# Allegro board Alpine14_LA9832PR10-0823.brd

Outline 316.05 x 177.2 mm; copper layers: TOP, GND1, IN1, VCC, IN2, IN3, GND2, BOTTOM. Coordinates in mm from the lower left corner of the outline.
Outline path: 0,104.74 arc(0.44,105.8) 1.5,106.24 28.86,106.24 arc(29.54,106.08) 30.08,105.62 arc(32.3,104.49) 34.52,105.62 arc(35.06,106.08) 35.74,106.24 50.28,106.24 arc(72.2,115.32) 81.28,137.24 81.28,142.24 arc(81.02,146.24) 80.25,150.17 arc(80.21,150.36) 80.2,150.55 80.2,158.02 arc(80.1,158.56) 79.81,159.03 74.64,164.67 arc(74.35,165.14) 74.25,165.68 74.25,173.8 arc(74.69,174.86) 75.75,175.3 111.8,175.3 arc(112.43,175.16) 112.95,174.76 113.55,174.04 arc(114.07,173.64) 114.7,173.5 130.83,173.5 arc(131.19,173.54) 131.53,173.67 133.07,174.48 arc(133.41,174.61) 133.77,174.65 198.63,174.65 arc(198.99,174.61) 199.33,174.48 200.87,173.67 arc(201.21,173.54) 201.57,173.5 219.2,173.5 arc(219.83,173.64) 220.35,174.04 220.95,174.76 arc(221.47,175.16) 222.1,175.3 282.93,175.3 arc(283.5,175.41) 283.99,175.74 285.01,176.76 arc(285.5,177.09) 286.07,177.2 314.55,177.2 arc(315.61,176.76) 316.05,175.7 316.05,146.8 arc(315.76,146.09) 315.05,145.8 313.55,145.8 arc(312.84,145.51) 312.55,144.8 312.55,144.6 arc(312.26,143.89) 311.55,143.6 237.58,143.6 arc(237.01,143.49) 236.52,143.16 211.9,118.54 arc(211.41,118.21) 210.84,118.1 198.85,118.1 arc(197.79,117.66) 197.35,116.6 197.35,77.49 arc(197.05,76.59) 196.26,76.05 arc(193.35,72.2) 196.26,68.35 arc(197.05,67.81) 197.35,66.91 197.35,62.95 arc(197.64,62.24) 198.35,61.95 198.85,61.95 arc(199.56,61.66) 199.85,60.95 199.85,15 arc(199.41,13.94) 198.35,13.5 193.9,13.5 arc(192.84,13.06) 192.4,12 192.4,2.5 arc(191.96,1.44) 190.9,1 100.9,1 arc(99.84,1.44) 99.4,2.5 99.4,8.4 arc(98.96,9.46) 97.9,9.9 16.8,9.9 arc(15.74,9.46) 15.3,8.4 15.3,1.5 arc(14.86,0.44) 13.8,0 6.9,0 arc(4.07,1.17) 2.9,4 2.9,8.75 arc(2.75,9.11) 2.4,9.25 2.2,9.25 arc(1.85,9.4) 1.7,9.75 1.7,37 arc(1.63,37.26) 1.44,37.44 arc(0.5,39.02) 1.44,40.6 arc(1.63,40.78) 1.7,41.04 1.7,65.25 arc(1.85,65.61) 2.2,65.75 2.4,65.75 arc(2.75,65.9) 2.9,66.25 2.9,68.6 arc(3.05,68.96) 3.4,69.1 13.96,69.1 arc(14.46,69.6) 13.96,70.1 13.46,70.1 arc(13.1,70.25) 12.96,70.6 12.96,81.1 arc(13.1,81.46) 13.46,81.6 13.96,81.6 arc(14.46,82.1) 13.96,82.6 3.15,82.6 arc(2.8,82.75) 2.65,83.1 2.65,86.55 arc(2.8,86.9) 3.15,87.05 9.93,87.05 arc(10.43,87.55) 9.93,88.05 9.93,101.55 arc(10.43,102.05) 9.93,102.55 0.5,102.55 arc(0.15,102.7) 0,103.05 0,104.74

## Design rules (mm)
net group BC_DAT-EC1117: nets BC_CLK_ECE1117 BC_DAT_ECE1117
net group BC_DAT_ECE5048: nets BC_CLK_ECE5048 BC_DAT_ECE5048
net group CL_LINK: nets PCH_CL_RST1# PCH_CL_RST1#_R
net group CLK_PCIE_EXP: nets CLK_PCIE_EXP CLK_PCIE_EXP#
net group CLK_PCIE_FMC: nets CLK_PCIE_FMC CLK_PCIE_FMC#
net group CLK_PCIE_MINI2: nets CLK_PCIE_MINI2 CLK_PCIE_MINI2#
net group CLK_PCIE_MMI: nets CLK_PCIE_MMI CLK_PCIE_MMI#
net group CLK_PEG_VGA: nets CLK_PEG_VGA CLK_PEG_VGA#
net group CLKA0: nets CLKA0 CLKA0#
net group CLKA1: nets CLKA1 CLKA1#
net group CPU_DPB_CTRLDAT: nets CPU_DPB_CTRLCLK CPU_DPB_CTRLDAT
net group CSS_1: nets CSSN_1 CSSP_1
net group DAT_DDC2_DOCK: nets CLK_DDC2_DOCK DAT_DDC2_DOCK
net group DAT_TP_SIO: nets CLK_TP_SIO DAT_TP_SIO
net group DCIN_JACK: nets +DCIN_JACK -DCIN_JACK
net group DDR_A_DQS0: nets DDR_A_DQS0 DDR_A_DQS#0
net group DDR_A_DQS1: nets DDR_A_DQS1 DDR_A_DQS#1
net group DDR_A_DQS2: nets DDR_A_DQS2 DDR_A_DQS#2
net group DDR_A_DQS3: nets DDR_A_DQS3 DDR_A_DQS#3
net group DDR_A_DQS4: nets DDR_A_DQS4 DDR_A_DQS#4
net group DDR_A_DQS6: nets DDR_A_DQS6 DDR_A_DQS#6
net group DDR_A_DQS7: nets DDR_A_DQS7 DDR_A_DQS#7
net group DDR_B_DQS0: nets DDR_B_DQS0 DDR_B_DQS#0
net group DDR_B_DQS1: nets DDR_B_DQS1 DDR_B_DQS#1
net group DDR_B_DQS2: nets DDR_B_DQS2 DDR_B_DQS#2
net group DDR_B_DQS4: nets DDR_B_DQS4 DDR_B_DQS#4
net group DDR_B_DQS5: nets DDR_B_DQS5 DDR_B_DQS#5
net group DDR_B_DQS6: nets DDR_B_DQS6 DDR_B_DQS#6
net group DDR_B_DQS7: nets DDR_B_DQS7 DDR_B_DQS#7
net group DDR_B_DQS#3: nets DDR_B_DQS3 DDR_B_DQS#3
net group DDR_XDP_SMBCLK_R1: nets DDR_XDP_SMBCLK_R1 DDR_XDP_SMBDAT_R1
net group DIFFPAIR0: nets DDR_A_DQS5 DDR_A_DQS#5
net group DIFFPAIR1: nets SATA_PRX_DTX_N1 SATA_PRX_DTX_P1
net group DIFFPAIR2: nets SATA_PTX_DRX_N1 SATA_PTX_DRX_P1
net group DIFFPAIR3: nets SATA_PRX_DTX_N1_C SATA_PRX_DTX_P1_C
net group DIFFPAIR4: nets SATA_PTX_DRX_N1_C SATA_PTX_DRX_P1_C
net group DIFFPAIR5: nets SATA_PRX_DKTX_N0_C SATA_PRX_DKTX_P0_C
net group DMIC_CLK0: nets DMIC0 DMIC_CLK0
net group DOCK_DCIN_IS: nets DOCK_DCIN_IS+ DOCK_DCIN_IS-
net group DPB_CA_DET: nets DPB_CA_DET DPB_CA_DET#
net group DPC_CA_DET: nets DPC_CA_DET DPC_CA_DET#
net group EDID_DATA_LCD: nets EDID_CLK_LCD EDID_DATA_LCD
net group EDP_CPU_AUX: nets EDP_CPU_AUX EDP_CPU_AUX#
net group EDP_CPU_AUX_C: nets EDP_CPU_AUX#_C EDP_CPU_AUX_C
net group EDP_CPU_LANE_0: nets EDP_CPU_LANE_N0 EDP_CPU_LANE_P0
net group EDP_CPU_LANE_0_C: nets EDP_CPU_LANE_N0_C EDP_CPU_LANE_P0_C
net group EDP_CPU_LANE_1: nets EDP_CPU_LANE_N1 EDP_CPU_LANE_P1
net group EDP_CPU_LANE_1_C: nets EDP_CPU_LANE_N1_C EDP_CPU_LANE_P1_C
net group GPU_SMBCLK: nets GPU_SMBCLK GPU_SMBDAT
net group HUB_USBP1_R_D: nets HUB_USBP1_R_D+ HUB_USBP1_R_D-
net group HUB_USBP4: nets HUB_USBP4+ HUB_USBP4-
net group HUB_USBP4_D: nets HUB_USBP4+_D HUB_USBP4-_D
net group INT_SPK_L: nets INT_SPK_L+ INT_SPK_L-
net group INT_SPK_R: nets INT_SPK_R+ INT_SPK_R-
net group NVVDD_SENSE: nets NVVDD_GND_SENSE NVVDD_SENSE
net group PCH_CL_CLK1: nets PCH_CL_CLK1 PCH_CL_DATA1
net group PCIE_PTX_EXPRX_C: nets PCIE_PTX_EXPRX_N_C PCIE_PTX_EXPRX_P_C
net group PEG_EXP: nets PEG_EXP PEG_EXP#
net group PS2_DAT_TS: nets PS2_CLK_TS PS2_DAT_TS
net group REM_DIODE1_: nets REM_DIODE1_N REM_DIODE1_P
net group REM_DIODE3: nets REM_DIODE3_N REM_DIODE3_P
net group REM_DIODE4_: nets REM_DIODE4_N REM_DIODE4_P
net group SATA_PTX_MSATARX_3: nets SATA_PTX_MSATARX_N3 SATA_PTX_MSATARX_P3
net group SATA_PTX_MSATARX_3_C: nets SATA_PTX_MSATARX_N3_C SATA_PTX_MSATARX_P3_C
net group SENSE: nets VCCSENSE VSSSENSE
net group SMB_15: nets BC_INT#_ECE1117 BC_INT#_ECE5048
net group SR_B: nets SRN_B SRP_B
net group THERMAL: nets REM_DIODE2_N REM_DIODE2_P
net group USB3R4: nets USB3RN4 USB3RP4
net group USB3RP4_D: nets USB3RN4_D- USB3RP4_D+
net group USB3T4: nets USB3TN4 USB3TP4
net group USB3TN1_RP_C: nets USB3TN1_RP_C USB3TP1_RP_C
net group USB3TP1_RP_CL: nets USB3TN1_RP_CL USB3TP1_RP_CL
net group USB3TP4_D: nets USB3TN4_D- USB3TP4_D+
net group USBP0: nets USBP0+ USBP0-
net group USBP2: nets USBP2+ USBP2-
net group 12: nets PCH_OPI_COMP PCH_PCIE_IREF PCH_PCIE_RCOMP SATA_COMP SATA_IREF
net group ASYNC: nets DDR3_DRAMRST# DDR3_DRAMRST#_CPU H_CPU_SVIDALRT# H_PROCHOT# H_PROCHOT#_R H_THERMTRIP# H_THERMTRIP#_R H_VCCST_PWRGD_XDP PECI_EC PECI_EC_R PROCHOT#_EC THERMATRIP2# VCCST_PWRGD VIDALERT_N VIDSCLK VIDSOUT XDP_OBS0_R XDP_OBS1_R
net group CLK-SRC: nets CLK_PCIE_LAN CLK_PCIE_LAN# PCIE_LAN PCIE_LAN# PCIE_MINI2 PCIE_MINI2# PCIE_MMI PCIE_MMI# PEG_VGA PEG_VGA# PEG_VGA_EXP PEG_VGA_EXP#
net group CLK_SINGAL: nets CLK_PCI_DOCK CLK_PCI_FBIN CLK_PCI_LPDEBUG CLK_PCI_MEC CLK_PCI_TPM_TCM EC_32KHZ_ECE5048 EC_32KHZ_ECE5048_R PCI_5048 PCI_CLK_LPC PCI_CLK_LPC_0 PCI_CLK_LPC_1 PCI_FBIN PCI_MEC PCI_TPM_TCM VMM_SPI_CLK
net group CR_LOW: nets DSWODVREN INTRUDER# PCH_DPWROK PCH_INTVRMEN PCH_PCIE_WAKE# PCH_RSMRST#_Q PCH_RSMRST#_R PCH_RTCRST# PM_APWROK SIO_PWRBTN# SIO_RCIN# SRTCRST# SYS_PWROK SYS_PWROK_R SYS_RESET#
net group CRT: nets BLUE_CRT BLUE_DOCK GREEN_CRT GREEN_DOCK RED_CRT RED_DOCK
net group CRT-SYNC: nets HSYNC_BUF HSYNC_DOCK VSYNC_BUF VSYNC_DOCK
net group DDRA-ADD: nets DDR_A_BS0 DDR_A_BS1 DDR_A_BS2 DDR_A_CAS# DDR_A_MA0 DDR_A_MA1 DDR_A_MA2 DDR_A_MA3 DDR_A_MA4 DDR_A_MA5 DDR_A_MA6 DDR_A_MA7 DDR_A_MA8 DDR_A_MA9 DDR_A_MA10 DDR_A_MA11 DDR_A_MA12 DDR_A_MA13 DDR_A_MA14 DDR_A_MA15 DDR_A_RAS# DDR_A_WE#
net group DDRA-CLK: nets M_CLK_DDR0 M_CLK_DDR1 M_CLK_DDR#0 M_CLK_DDR#1
net group DDRA-CTL: nets DDR_CKE0_DIMMA DDR_CKE1_DIMMA DDR_CS0_DIMMA# DDR_CS1_DIMMA# M_ODT0 M_ODT1
net group DDRB-ADD: nets DDR_B_BS0 DDR_B_BS1 DDR_B_BS2 DDR_B_CAS# DDR_B_MA0 DDR_B_MA1 DDR_B_MA2 DDR_B_MA3 DDR_B_MA4 DDR_B_MA5 DDR_B_MA6 DDR_B_MA7 DDR_B_MA8 DDR_B_MA9 DDR_B_MA10 DDR_B_MA11 DDR_B_MA12 DDR_B_MA13 DDR_B_MA14 DDR_B_MA15 DDR_B_RAS# DDR_B_WE#
net group DDRB-CLK: nets M_CLK_DDR2 M_CLK_DDR3 M_CLK_DDR#2 M_CLK_DDR#3
net group DDRB-CTL: nets DDR_CKE2_DIMMB DDR_CKE3_DIMMB DDR_CS2_DIMMB# DDR_CS3_DIMMB# M_ODT2 M_ODT3
net group DDRB-D0: nets DDR_B_D0 DDR_B_D1 DDR_B_D2 DDR_B_D3 DDR_B_D4 DDR_B_D5 DDR_B_D6 DDR_B_D7
net group DDRB-D1: nets DDR_B_D8 DDR_B_D9 DDR_B_D10 DDR_B_D11 DDR_B_D12 DDR_B_D13 DDR_B_D14 DDR_B_D15
net group DDRB-D2: nets DDR_B_D16 DDR_B_D17 DDR_B_D18 DDR_B_D19 DDR_B_D20 DDR_B_D21 DDR_B_D22 DDR_B_D23
net group DDRB-D3: nets DDR_B_D24 DDR_B_D25 DDR_B_D26 DDR_B_D27 DDR_B_D28 DDR_B_D29 DDR_B_D30 DDR_B_D31
net group DDRB-D4: nets DDR_B_D32 DDR_B_D33 DDR_B_D34 DDR_B_D35 DDR_B_D36 DDR_B_D37 DDR_B_D38 DDR_B_D39
net group DDRB-D5: nets DDR_B_D40 DDR_B_D41 DDR_B_D42 DDR_B_D43 DDR_B_D44 DDR_B_D45 DDR_B_D46 DDR_B_D47
net group DDRB-D6: nets DDR_B_D48 DDR_B_D49 DDR_B_D50 DDR_B_D51 DDR_B_D52 DDR_B_D53 DDR_B_D54 DDR_B_D55
net group DDRB-D7: nets DDR_B_D56 DDR_B_D57 DDR_B_D58 DDR_B_D59 DDR_B_D60 DDR_B_D61 DDR_B_D62 DDR_B_D63
net group DDRD0_8_16_20: nets DDR_A_D8 DDR_A_D9 DDR_A_D10 DDR_A_D11 DDR_A_D12 DDR_A_D13 DDR_A_D14 DDR_A_D15 DDR_A_D24 DDR_A_D25 DDR_A_D26 DDR_A_D27 DDR_A_D28 DDR_A_D29 DDR_A_D30 DDR_A_D31 DDR_A_D32 DDR_A_D33 DDR_A_D34 DDR_A_D35 DDR_A_D36 DDR_A_D37 DDR_A_D38 DDR_A_D39 DDR_A_D48 DDR_A_D49 DDR_A_D50 DDR_A_D51 DDR_A_D52 DDR_A_D53 DDR_A_D54 DDR_A_D55
net group DDRD1_8_16_20: nets DDR_A_D0 DDR_A_D1 DDR_A_D2 DDR_A_D3 DDR_A_D4 DDR_A_D5 DDR_A_D6 DDR_A_D7 DDR_A_D16 DDR_A_D17 DDR_A_D18 DDR_A_D19 DDR_A_D20 DDR_A_D21 DDR_A_D22 DDR_A_D23 DDR_A_D40 DDR_A_D41 DDR_A_D42 DDR_A_D43 DDR_A_D44 DDR_A_D45 DDR_A_D46 DDR_A_D47 DDR_A_D56 DDR_A_D57 DDR_A_D58 DDR_A_D59 DDR_A_D60 DDR_A_D61 DDR_A_D62 DDR_A_D63
net group DP: nets CPU_DPB_AUX CPU_DPB_AUX# CPU_DPB_AUX#_C CPU_DPB_AUX_C DDI1_LANE_N0 DDI1_LANE_N0_C DDI1_LANE_N1 DDI1_LANE_N1_C DDI1_LANE_N2 DDI1_LANE_N2_C DDI1_LANE_N3 DDI1_LANE_N3_C DDI1_LANE_P0 DDI1_LANE_P0_C DDI1_LANE_P1 DDI1_LANE_P1_C DDI1_LANE_P2 DDI1_LANE_P2_C DDI1_LANE_P3 DDI1_LANE_P3_C
net group DP_VMM: nets DPB_DOCK_AUX DPB_DOCK_AUX# DPB_DOCK_LANE_N0 DPB_DOCK_LANE_N1 DPB_DOCK_LANE_N2 DPB_DOCK_LANE_N3 DPB_DOCK_LANE_P0 DPB_DOCK_LANE_P1 DPB_DOCK_LANE_P2 DPB_DOCK_LANE_P3 DPB_LANE_N0 DPB_LANE_N0_C DPB_LANE_N1 DPB_LANE_N1_C DPB_LANE_N2 DPB_LANE_N2_C DPB_LANE_N3 DPB_LANE_N3_C DPB_LANE_P0 DPB_LANE_P0_C DPB_LANE_P1 DPB_LANE_P1_C DPB_LANE_P2 DPB_LANE_P2_C DPB_LANE_P3 DPB_LANE_P3_C DPC_DOCK_AUX DPC_DOCK_AUX# DPC_DOCK_LANE_N0 DPC_DOCK_LANE_N1 DPC_DOCK_LANE_N2 DPC_DOCK_LANE_N3 DPC_DOCK_LANE_P0 DPC_DOCK_LANE_P1 DPC_DOCK_LANE_P2 DPC_DOCK_LANE_P3 DPC_LANE_N0 DPC_LANE_N0_C DPC_LANE_N1 DPC_LANE_N1_C DPC_LANE_N2 DPC_LANE_N2_C DPC_LANE_N3 DPC_LANE_N3_C DPC_LANE_P0 DPC_LANE_P0_C DPC_LANE_P1 DPC_LANE_P1_C DPC_LANE_P2 DPC_LANE_P2_C DPC_LANE_P3 DPC_LANE_P3_C SW_DPB_AUX SW_DPB_AUX# SW_DPB_AUX#_C SW_DPB_AUX_C SW_DPC_AUX SW_DPC_AUX# SW_DPC_AUX#_C SW_DPC_AUX_C VMM2310_CLK_DDC2 VMM2310_DAT_DDC2
net group EXP: nets EXP_PRX_EXPTX_N6 EXP_PRX_EXPTX_N6_CL EXP_PRX_EXPTX_N6_M EXP_PRX_EXPTX_P6 EXP_PRX_EXPTX_P6_CL EXP_PRX_EXPTX_P6_M EXP_PTX_EXPRX_N6 EXP_PTX_EXPRX_N6_CL EXP_PTX_EXPRX_N6_M EXP_PTX_EXPRX_P6 EXP_PTX_EXPRX_P6_CL EXP_PTX_EXPRX_P6_M
net group HDA: nets PCH_AZ_BITCLK PCH_AZ_CODEC_BITCLK PCH_AZ_CODEC_RST# PCH_AZ_CODEC_SDIN0 PCH_AZ_CODEC_SDOUT PCH_AZ_CODEC_SYNC PCH_AZ_RST# PCH_AZ_SDIN0_R PCH_AZ_SDOUT PCH_AZ_SYNC
net group HDMI: nets TMDS_CLK TMDS_CLK# TMDS_N0 TMDS_N1 TMDS_N2 TMDS_P0 TMDS_P1 TMDS_P2 TMDS_RP_CLK TMDS_RP_CLK# TMDS_RP_N0 TMDS_RP_N1 TMDS_RP_N2 TMDS_RP_P0 TMDS_RP_P1 TMDS_RP_P2 TMDSB_CON_CLK TMDSB_CON_CLK# TMDSB_CON_N0 TMDSB_CON_N1 TMDSB_CON_N2 TMDSB_CON_P0 TMDSB_CON_P1 TMDSB_CON_P2
net group I2C: nets I2C0_SCL I2C0_SDA I2C1_SCL_TCH_PAD I2C1_SCL_VMM I2C1_SDA_TCH_PAD I2C1_SDA_VMM N17049026 N17049030 TMDS_DDC_SCL TMDS_DDC_SCL_R TMDS_DDC_SDA TMDS_DDC_SDA_R TP_CLK TP_DATA
net group I2S: nets DAI_12MHZ# DAI_BCLK# DAI_DI DAI_DO# DAI_LRCK# I2S_BCLK I2S_DI# I2S_DO I2S_LRCLK I2S_MCLK
net group LPC: nets CLK_PCI_5048 CLKRUN# D_CLKRUN# D_DLDRQ1# D_LAD0 D_LAD1 D_LAD2 D_LAD3 D_LFRAME# D_SERIRQ LPC_LAD0 LPC_LAD1 LPC_LAD2 LPC_LAD3 LPC_LFRAME# PCH_PLTRST#_EC
net group LVDS: nets PCH_TXCLK+ PCH_TXCLK- PCH_TXOUT0+ PCH_TXOUT0- PCH_TXOUT1+ PCH_TXOUT1- PCH_TXOUT2+ PCH_TXOUT2- PCH_TZCLK+ PCH_TZCLK- PCH_TZOUT0+ PCH_TZOUT0- PCH_TZOUT1+ PCH_TZOUT1- PCH_TZOUT2+ PCH_TZOUT2-
net group MDI: nets DOCK_LOM_TRD0+ DOCK_LOM_TRD0- DOCK_LOM_TRD1+ DOCK_LOM_TRD1- DOCK_LOM_TRD2+ DOCK_LOM_TRD2- DOCK_LOM_TRD3+ DOCK_LOM_TRD3- LAN_TX0+ LAN_TX0+R LAN_TX0- LAN_TX0-R LAN_TX1+ LAN_TX1+R LAN_TX1- LAN_TX1-R LAN_TX2+ LAN_TX2+R LAN_TX2- LAN_TX2-R LAN_TX3+ LAN_TX3+R LAN_TX3- LAN_TX3-R SW_LAN_TX0+ SW_LAN_TX0- SW_LAN_TX1+ SW_LAN_TX1- SW_LAN_TX2+ SW_LAN_TX2- SW_LAN_TX3+ SW_LAN_TX3-
net group PCIE: nets PCIE_PRX_EXPTX_N PCIE_PRX_EXPTX_N_M PCIE_PRX_EXPTX_P PCIE_PRX_EXPTX_P_M PCIE_PRX_GLANTX_N3 PCIE_PRX_GLANTX_N3_C PCIE_PRX_GLANTX_P3 PCIE_PRX_GLANTX_P3_C PCIE_PRX_MMITX_N1 PCIE_PRX_MMITX_N1_C PCIE_PRX_MMITX_P1 PCIE_PRX_MMITX_P1_C PCIE_PRX_WLANTX_N4 PCIE_PRX_WLANTX_P4 PCIE_PTX_EXPRX_N PCIE_PTX_EXPRX_N_M PCIE_PTX_EXPRX_P PCIE_PTX_EXPRX_P_M PCIE_PTX_GLANRX_N3 PCIE_PTX_GLANRX_N3_C PCIE_PTX_GLANRX_P3 PCIE_PTX_GLANRX_P3_C PCIE_PTX_MMIRX_N1 PCIE_PTX_MMIRX_N1_C PCIE_PTX_MMIRX_P1 PCIE_PTX_MMIRX_P1_C PCIE_PTX_WLANRX_N4 PCIE_PTX_WLANRX_N4_C PCIE_PTX_WLANRX_P4 PCIE_PTX_WLANRX_P4_C
net group PEG: nets PEG_GTX_C_HRX_N0 PEG_GTX_C_HRX_N0_M PEG_GTX_C_HRX_N0_R PEG_GTX_C_HRX_N1 PEG_GTX_C_HRX_N2 PEG_GTX_C_HRX_N3 PEG_GTX_C_HRX_P0 PEG_GTX_C_HRX_P0_M PEG_GTX_C_HRX_P0_R PEG_GTX_C_HRX_P1 PEG_GTX_C_HRX_P2 PEG_GTX_C_HRX_P3 PEG_GTX_HRX_N0 PEG_GTX_HRX_N1 PEG_GTX_HRX_N2 PEG_GTX_HRX_N3 PEG_GTX_HRX_P0 PEG_GTX_HRX_P1 PEG_GTX_HRX_P2 PEG_GTX_HRX_P3 PEG_HTX_C_GRX_N0 PEG_HTX_C_GRX_N1 PEG_HTX_C_GRX_N2 PEG_HTX_C_GRX_N3 PEG_HTX_C_GRX_P0 PEG_HTX_C_GRX_P1 PEG_HTX_C_GRX_P2 PEG_HTX_C_GRX_P3 PEG_HTX_GRX_N0 PEG_HTX_GRX_N0_M PEG_HTX_GRX_N1 PEG_HTX_GRX_N2 PEG_HTX_GRX_N3 PEG_HTX_GRX_P0 PEG_HTX_GRX_P0_M PEG_HTX_GRX_P1 PEG_HTX_GRX_P2 PEG_HTX_GRX_P3
net group POWER: nets +1.35V_MEM
net group RCOMP: nets SM_RCOMP0 SM_RCOMP1 SM_RCOMP2
net group SATA: nets SATA_PRX_DKTX_N0 SATA_PRX_DKTX_P0 SATA_PRX_MSATATX_N3 SATA_PRX_MSATATX_N3_M SATA_PRX_MSATATX_P3 SATA_PRX_MSATATX_P3_M SATA_PTX_DKRX_N0 SATA_PTX_DKRX_N0_C SATA_PTX_DKRX_P0 SATA_PTX_DKRX_P0_C SATA_PTX_MSATARX_N3_M SATA_PTX_MSATARX_P3_M
net group SD2: nets SD/MMCCD# SD/MMCCLK SD/MMCCLK_R SD/MMCCMD SD/MMCDAT2 SD/MMCDAT2_R SD/MMCDAT3 SD/MMCDAT3_R SD_RCLK+ SD_RCLK+_D SD_RCLK- SD_RCLK-_D SD_UHS2_D0N SD_UHS2_D0N_D SD_UHS2_D0P SD_UHS2_D0P_D SD_UHS2_D1N SD_UHS2_D1N_D SD_UHS2_D1P SD_UHS2_D1P_D SDWP
net group SIM: nets UIM_CLK UIM_DATA UIM_RESET UIM_VPP
net group SMB: nets CARD_SMBCLK CARD_SMBDAT CHARGER_SMBCLK CHARGER_SMBDAT CIICSCL CIICSDA CLK_KBD CLK_MSE DAT_KBD DAT_MSE DDR_XDP_WAN_SMBCLK DDR_XDP_WAN_SMBDAT DMIC1 DMIC_CLK1 DMIC_CLK_L DOCK_SMB_CLK DOCK_SMB_DAT EDID_CLK EDID_DATA LAN_SMBCLK LAN_SMBDATA MEM_SMBCLK MEM_SMBDATA PBAT_SMBCLK PBAT_SMBDAT RTD2136_SCL RTD2136_SDA SML1_SMBCLK SML1_SMBDATA USH_SMBCLK USH_SMBDAT VMM_DPB_CTRLCLK VMM_DPB_CTRLDAT VMM_DPC_CTRLCLK VMM_DPC_CTRLDAT VMM_MESCL VMM_MESDA WWAN_SMBCLK WWAN_SMBDAT
net group SPI: nets PCH_SPI_CLK PCH_SPI_CS0# PCH_SPI_CS1# PCH_SPI_DIN PCH_SPI_DO PCH_SPI_DO2 PCH_SPI_DO3 SPI_CLK32 SPI_CLK64 SPI_DIN32 SPI_DIN64 SPI_DO32 SPI_DO64 SPI_PCH_CS0#_R SPI_PCH_CS1#_R SPI_PCH_DO2_32 SPI_PCH_DO2_64 SPI_PCH_DO3_32 SPI_PCH_DO3_64 TAA_CLK32 TAA_CLK64 TAA_CS0#_R TAA_CS1#_R TAA_DIN32 TAA_DIN64 TAA_DO2_32 TAA_DO2_64 TAA_DO3_32 TAA_DO3_64 TAA_DO32 TAA_DO64 VMM_SPI_CS# VMM_SPI_DIN VMM_SPI_DO
net group SPK: nets INT_SPKR_L+ INT_SPKR_L- INT_SPKR_R+ INT_SPKR_R-
net group USB20: nets DOCK_USBP1+ DOCK_USBP1- DOCK_USBP1_D+ DOCK_USBP1_D- DOCK_USBP2+ DOCK_USBP2- DOCK_USBP2_D+ DOCK_USBP2_D- HUB_USBP1+ HUB_USBP1- HUB_USBP2+ HUB_USBP2+_D HUB_USBP2- HUB_USBP2-_D HUB_USBP3+ HUB_USBP3- USBP1+ USBP1- USBP1_R_D+ USBP1_R_D- USBP5+ USBP5- USBP5_D+ USBP6+ USBP6- USBP6_D+ USBP6_D- USBP7+ USBP7+_D USBP7- USBP7-_D
net group USB30: nets USB3RN0 USB3RN0_D- USB3RN1 USB3RN1_C USB3RN1_R USB3RN1_R_CL USB3RN1_RC USB3RP0 USB3RP0_D+ USB3RP1 USB3RP1_C USB3RP1_R USB3RP1_R_CL USB3RP1_RC USB3TN0 USB3TN0_C USB3TN0_D- USB3TN1 USB3TN1_C USB3TN1_RP USB3TP0 USB3TP0_C USB3TP0_D+ USB3TP1 USB3TP1_C USB3TP1_RP
net group USBP5_D: nets USBP5_D-
net group VRAM_CMD: nets FBA_CMD0 FBA_CMD2 FBA_CMD3 FBA_CMD4 FBA_CMD5 FBA_CMD6 FBA_CMD7 FBA_CMD8 FBA_CMD9 FBA_CMD10 FBA_CMD11 FBA_CMD12 FBA_CMD13 FBA_CMD14 FBA_CMD15 FBA_CMD16 FBA_CMD18 FBA_CMD19 FBA_CMD20 FBA_CMD21 FBA_CMD22 FBA_CMD23 FBA_CMD24 FBA_CMD25 FBA_CMD26 FBA_CMD27 FBA_CMD28 FBA_CMD29 FBA_CMD30
net group VRAM_D0: nets DQMA0 FBA_D0 FBA_D1 FBA_D2 FBA_D3 FBA_D4 FBA_D5 FBA_D6 FBA_D7
net group VRAM_D1: nets DQMA1 FBA_D8 FBA_D9 FBA_D10 FBA_D11 FBA_D12 FBA_D13 FBA_D14 FBA_D15
net group VRAM_D2: nets DQMA2 FBA_D16 FBA_D17 FBA_D18 FBA_D19 FBA_D20 FBA_D21 FBA_D22 FBA_D23
net group VRAM_D3: nets DQMA3 FBA_D24 FBA_D25 FBA_D26 FBA_D27 FBA_D28 FBA_D29 FBA_D30 FBA_D31
net group VRAM_D4: nets DQMA4 FBA_D32 FBA_D33 FBA_D34 FBA_D35 FBA_D36 FBA_D37 FBA_D38 FBA_D39
net group VRAM_D5: nets DQMA5 FBA_D40 FBA_D41 FBA_D42 FBA_D43 FBA_D44 FBA_D45 FBA_D46 FBA_D47
net group VRAM_D6: nets DQMA6 FBA_D48 FBA_D49 FBA_D50 FBA_D51 FBA_D52 FBA_D53 FBA_D54 FBA_D55
net group VRAM_D7: nets DQMA7 FBA_D56 FBA_D57 FBA_D58 FBA_D59 FBA_D60 FBA_D61 FBA_D62 FBA_D63
net group VRAM_DQS: nets QSA0 QSA1 QSA2 QSA3 QSA4 QSA5 QSA6 QSA7 QSA#0 QSA#1 QSA#2 QSA#3 QSA#4 QSA#5 QSA#6 QSA#7
nets with their own width: min track width 0.254; nets BAT1_LED# BAT2_LED# BATT_WHITE_LED# BATT_YELLOW_LED# CLK_BIASREF N17205976 N61090377 VDDA18CR VDDA18PLL XTAL24M_IN XTAL24M_OUT
nets with their own width: min track width 0.381; nets AUD_HP_OUT_L AUD_HP_OUT_R
nets with their own width: min track width 0.508; nets +0.675V_P +1.2V_LDO +1.2V_LDO_AIN +1.05V_GPU +1.5V_GPU +1.05V_M_JTAG +1.05V_MODPHY +1.05V_MP +1.05V_RUN +1.5V_RUNP +1.5V_THERMAL +1.05V_VCCST +1.8V_RUN_CARD +1.35V_MEN_P +3.3V_ALW +3.3V_ALW2 +3.3V_ALW_5048 +3.3V_ALW_5075 +3.3V_ALW_PCH_U41 +3.3V_ALWP +3.3V_AVCC +3.3V_CAM +3.3V_GPU +3.3V_HDD +3.3V_LAN +3.3V_LAN_OUT +3.3V_M +3.3V_PCIE_WWAN +3.3V_RUN +3.3V_RUN_AIN +3.3V_RUN_AUDIO +3.3V_RUN_CARD +3.3V_RUN_FFS +3.3V_RUN_TPM +3.3V_RUN_VDDA +3.3V_SUS +3.3V_TP +3.3V_USBHUB +3.3V_VTR +3.3V_VTR_ADC +5V_ALW +5V_ALW2 +5V_ALWP +5V_HDMI_DDC +5V_RUN +5V_RUN_AUDIO +5V_TSP +5V_TSP_Q +ALC290_LDO_CAP +ALC3226_CPVEE +ALC3226_VREF +AUX_LDO +BATT_SUM +CAP_LDO +CHGR_DC_IN +COINCELL +DC1_PWR_SRC +DC_IN +DC_IN_SS +DCIN +DCPRRTC +DIMM1_VREF_DQ +DIMM2_VREF_DQ +DVDD_CORE +FB_PLLAVDD +GPU_CORE +NBDOCK_DC_IN_SS +P1.05V_PEX_VDD +PBATT +PBATT_IN_SS +PCH_ASATA3PLL +PCH_AUSB3PLL +PCH_DCPSUS +PCH_DCPSUS1 +PCH_DCPSUS4 +PCH_RTC_VCCSUS3_3 +PCH_VCC1P05 +PCH_VCCACLKPLL +PCH_VCCDSW +PCH_VCCDSW_R +PECI_VREF +PNVVDD +PWR_SRC +PWR_SRC_AC +RSVD_VCC3P3_1 +RTC_CELL +RTC_CELL_VBAT +SD_IO_LDO +SDC_IN +SIM_PWR +SM_VREF_CA +SM_VREF_CA_DIMM +SM_VREF_CA_DIMMA +SM_VREF_CA_DIMMB +SM_VREF_DQ0 +SM_VREF_DQ0_DIMM1 +SM_VREF_DQ1 +SM_VREF_DQ1_DIMM2 +V1.05S_APLLOPI +V1.05SP_B+ +V_DDR_REF +VCC_CORE +VCC_PWR_SRC +VCCIO_OUT +VCCIOA_OUT +VCHGR +VDDA_AVDD1 +VDDA_AVDD2 +VDDRP +VDDRP_B+ +VLDOIN_1.35V +VR_CAP +VREFC_UV5 +VREFC_UV7 +VREFD_UV5 +VREFD_UV7 +VREFOUT EDP_COMP GND GNDA GNDA_CHG HDMI_OB PEX_PLLVDD_GPU RES_BIAS USX2064_RBIAS
nets with their own width: min track width 1.016; nets +1.05V_VMM_VDD +3.3V_RUN_VDDIO +DOCK_PWR_BAR +LOM_VCT +PCH_VCCDSW3_3 +VDDA_PVDD +VHDMI_VCC RING2 SLEEVE
nets with their own width: min track width 1.524; nets +0.675V_DDR_VTT +1.05V_M +1.05V_VMM_VDDTX +3.3V_DVCC +3.3V_HDD_C +5V_HDD +5V_MOD +BL_PWR_SRC +SWR_LX +SWR_V12
nets with their own width: min track width 2.032; nets +0.9V_LAN +1.05V_MODPHY_PCH +1.5V_RUN +3.3V_ALW_PCH +3.3V_WLAN +5V_USB_CHG_PWR +LCDVDD

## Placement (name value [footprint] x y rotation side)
C3  10U_0603_6.3V6M~D  [C_0603]  96.43 72 180 top
C5  0.1U_0402_25V6K~D  [C_0402]  30.28 17.58 180 bottom
C6  0.1U_0402_25V6K~D  [C_0402]  25.95 11.92 90 bottom
C7  22U_0805_6.3V6M~D  [C_0805]  73.28 98 270 top
C8  1U_0603_10V6K~D  [C_0603]  110.91 100.45 90 top
C9  0.1U_0402_25V6K~D  [C_0402]  121.45 112.18 90 top
C10  0.01U_0402_16V7K~D  [C_0402]  113 100.63 90 top
C11  0.1U_0402_25V6K~D  [C_0402]  120.56 112.18 90 top
C12  0.01U_0402_16V7K~D  [C_0402]  112.05 100.63 90 top
C13  0.01U_0402_16V7K~D  [C_0402]  122.34 112.18 90 top
C14  0.01U_0402_16V7K~D  [C_0402]  125.83 112.12 90 top
C15  0.1U_0402_25V6K~D  [C_0402]  127.53 102.8 0 top
C16  1U_0603_10V6K~D  [C_0603]  127.23 112.13 90 top
C17  0.1U_0402_25V6K~D  [C_0402]  127.53 104.45 0 top
C18  0.01U_0402_16V7K~D  [C_0402]  127.53 105.34 0 top
C19  0.1U_0402_10V7K~D  [C_0402]  123.22 95.97 90 top
C20  0.1U_0402_10V7K~D  [C_0402]  122.33 95.97 90 top
C21  1U_0603_10V6K~D  [C_0603]  111.54 98.35 270 top
C22  0.1U_0402_25V6K~D  [C_0402]  112.62 98.11 270 top
C23  0.01U_0402_16V7K~D  [C_0402]  113.58 98.11 270 top
C24  0.01U_0402_16V7K~D  [C_0402]  119.54 112.18 90 top
C25  1U_0603_10V6K~D  [C_0603]  109.26 101.72 90 top
C26  1U_0603_10V6K~D  [C_0603]  114.53 112.39 0 top
C27  0.1U_0402_25V6K~D  [C_0402]  118.65 112.18 90 top
C28  0.01U_0402_16V7K~D  [C_0402]  116.88 112.18 90 top
C29  0.01U_0402_16V7K~D  [C_0402]  117.76 112.18 90 top
C30  4.7U_0603_6.3V6K~D  [C_0603]  93.86 79.18 180 top
C34  0.1U_0402_25V6K~D  [C_0402]  95.62 87.3 180 top
C42  18P_0402_50V8J  [C_0402]  125 94.43 270 top
C43  18P_0402_50V8J  [C_0402]  127.66 96.76 0 top
C50  1U_0603_10V6K~D  [C_0603]  43.15 63.55 90 bottom
C73  0.1U_0402_25V6K~D  [C_0402]  93.9 77.87 180 top
C75  0.1U_0402_25V6K~D  [C_0402]  99.97 76.19 180 top
C76  33P_0402_50V8J~D  [C_0402]  28.74 13.28 270 bottom
C85  33P_0402_50V8J~D  [C_0402]  23.21 17.57 90 bottom
C87  0.1U_0402_10V7K~D  [C_0402]  14.76 100.89 0 top
C88  10U_0805_10V6K  [C_0805]  14.36 99.5 0 top
C93  0.1U_0402_25V6K~D  [C_0402]  144.31 144.63 90 top
C94  0.1U_0402_10V7K~D  [C_0402]  146.4 138.24 270 top
C95  0.1U_0402_10V7K~D  [C_0402]  147.29 138.24 270 top
C97  0.1U_0402_25V6K~D  [C_0402]  151.36 147.43 90 top
C98  0.1U_0402_10V7K~D  [C_0402]  152.63 138.43 270 top
C99  0.1U_0402_10V7K~D  [C_0402]  153.51 138.5 270 top
C101  10U_0603_6.3V6M~D  [C_0603]  161.01 123.24 0 top
C102  0.1U_0402_25V6K~D  [C_0402]  162.66 125.23 270 top
C103  0.1U_0402_10V7K~D  [C_0402]  21 97.97 0 bottom
C105  0.01U_0402_16V7K~D  [C_0402]  83.29 105.99 270 bottom
C106  0.01U_0402_16V7K~D  [C_0402]  82.4 105.99 270 bottom
C108  0.01U_0402_16V7K~D  [C_0402]  80.62 107.83 270 bottom
C109  0.01U_0402_16V7K~D  [C_0402]  81.51 107.83 270 bottom
C111  1000P_0402_50V7K~D  [C_0402]  82.33 130.09 90 bottom
C112  0.1U_0402_25V6K~D  [C_0402]  82.33 128.91 270 bottom
C113  0.1U_0402_25V6K~D  [C_0402]  86.98 117.09 180 top
C114  0.1U_0402_25V6K~D  [C_0402]  86.98 116.13 180 top
C115  0.1U_0402_25V6K~D  [C_0402]  258.1 147.2 270 bottom
C116  10U_0805_10V6K  [C_0805]  243.62 148.23 270 bottom
C117  10U_0805_10V6K  [C_0805]  264.58 147.72 270 bottom
C118  1U_0603_10V6K~D  [C_0603]  252.32 158.61 180 bottom
C119  0.1U_0402_25V6K~D  [C_0402]  257.09 158.66 90 bottom
C120  0.1U_0402_25V6K~D  [C_0402]  253.27 158.41 90 bottom
C121  10U_0805_10V6K  [C_0805]  250.38 156.96 180 bottom
C122  10U_0805_10V6K  [C_0805]  241.3 151.31 180 top
C123  0.1U_0402_25V6K~D  [C_0402]  249.61 150.74 180 bottom
C124  1000P_0402_50V7K~D  [C_0402]  203.75 122.3 270 top
C125  1000P_0402_50V7K~D  [C_0402]  203.75 123.23 90 top
C126  1000P_0402_50V7K~D  [C_0402]  203.75 126.05 270 top
C127  1000P_0402_50V7K~D  [C_0402]  203.75 126.98 90 top
C128  10U_0805_10V6K  [C_0805]  241.3 153.47 180 top
C129  0.1U_0402_25V6K~D  [C_0402]  249.61 154.68 180 bottom
C130  22P_0402_50V8J  [C_0402]  249.85 158.47 90 bottom
C131  1U_0603_10V4Z~D  [C_0603]  261.53 145.98 90 bottom
C133  0.1U_0402_25V6K~D  [C_0402]  258.22 162.17 0 bottom
C134  2.2U_0603_6.3V6K~D  [C_0603]  249.15 147.88 0 bottom
C135  0.1U_0402_10V7K~D  [C_0402]  254.29 160.19 90 bottom
C136  10P_0402_50V8J~D  [C_0402]  255.18 160.19 90 bottom
C137  0.1U_0402_25V6K~D  [C_0402]  263.24 161.27 90 bottom
C138  2.2U_0603_6.3V6K~D  [C_0603]  252.32 146.61 180 bottom
C139  22P_0402_50V8J  [C_0402]  245.33 157.6 0 bottom
C140  10U_0805_10V6K  [C_0805]  261.38 151.44 0 bottom
C141  0.1U_0402_25V6K~D  [C_0402]  267.12 151.93 90 bottom
C142  0.1U_0402_25V6K~D  [C_0402]  302.93 156.06 90 bottom
C143  0.1U_0402_25V6K~D  [C_0402]  258.22 161.28 0 bottom
C144  0.1U_0402_25V6K~D  [C_0402]  246.67 149.71 90 bottom
C145  1U_0603_10V6K~D  [C_0603]  253.08 168.9 90 top
C147  1000P_0402_50V7K~D  [C_0402]  251.88 167.26 270 bottom
C148  470P_0402_50V7K~D  [C_0402]  249.34 167.26 270 bottom
C149  1U_0603_10V6K~D  [C_0603]  248.13 168.9 90 top
C150  0.1U_0402_25V6K~D  [C_0402]  249.61 149.85 180 bottom
C152  470P_0402_50V7K~D  [C_0402]  76.31 86.73 180 bottom
C153  1U_0603_10V6K~D  [C_0603]  77.7 88.51 0 bottom
C154  1U_0603_10V6K~D  [C_0603]  77.51 83.81 0 bottom
C155  0.1U_0402_10V7K~D  [C_0402]  122.01 93.94 90 top
C156  0.1U_0402_10V7K~D  [C_0402]  121.12 93.94 90 top
C157  0.1U_0402_10V7K~D  [C_0402]  120.94 95.99 90 top
C158  0.1U_0402_10V7K~D  [C_0402]  119.99 95.99 90 top
C159  0.1U_0402_10V7K~D  [C_0402]  119.6 93.94 90 top
C160  0.1U_0402_10V7K~D  [C_0402]  118.71 93.94 90 top
C161  0.1U_0402_10V7K~D  [C_0402]  118.39 95.97 90 top
C162  0.1U_0402_10V7K~D  [C_0402]  117.44 95.97 90 top
C163  470P_0402_50V7K~D  [C_0402]  76.31 85.78 180 bottom
C167  0.1U_0402_25V6K~D  [C_0402]  259.05 146.28 90 bottom
C169  2.2U_0603_10V6K  [C_0603]  260.26 147.37 270 bottom
C176  0.1U_0402_10V7K~D  [C_0402]  173.25 140.54 180 top
C177  0.1U_0402_10V7K~D  [C_0402]  177.52 130.5 270 top
C178  0.1U_0402_10V7K~D  [C_0402]  172.34 139.59 0 top
C179  0.1U_0402_10V7K~D  [C_0402]  173.25 141.43 180 top
C180  10U_0603_6.3V6M~D  [C_0603]  173.01 136.64 180 top
C181  0.1U_0402_10V7K~D  [C_0402]  172.34 138.7 0 top
C182  1U_0603_10V6K~D  [C_0603]  185.26 135.82 180 top
C183  0.1U_0402_10V7K~D  [C_0402]  173.28 142.36 180 top
C184  0.1U_0402_10V7K~D  [C_0402]  182.08 133.4 0 top
C185  0.1U_0402_10V7K~D  [C_0402]  183.79 137.72 0 top
C186  0.1U_0402_10V7K~D  [C_0402]  183.79 140.01 0 top
C188  22U_0805_6.3V6M~D  [C_0805]  186.09 130.95 270 top
C189  27P_0402_50V8J  [C_0402]  180.25 129.84 90 top
C190  27P_0402_50V8J  [C_0402]  181.2 131.61 90 top
C191  0.1U_0402_10V7K~D  [C_0402]  21.01 98.86 0 bottom
C192  0.1U_0402_25V6K~D  [C_0402]  178.53 159.11 90 top
C193  0.1U_0402_25V6K~D  [C_0402]  190.62 159.49 90 top
C194  0.1U_0402_25V6K~D  [C_0402]  184.5 161.65 90 top
C198  0.1U_0402_10V7K~D  [C_0402]  181.32 147.31 0 top
C199  0.1U_0402_10V7K~D  [C_0402]  21 100.26 0 bottom
C200  0.1U_0402_25V6K~D  [C_0402]  162.72 118.24 270 top
C201  4700P_0402_25V7K~D  [C_0402]  158.66 117.33 90 top
C202  2200P_0402_50V7K~D  [C_0402]  162.22 108.21 270 top
C203  2200P_0402_50V7K~D  [C_0402]  158.09 108.14 270 top
C204  0.1U_0402_25V6K~D  [C_0402]  157.77 117.33 90 top
C206  4.7U_0603_6.3V6K~D  [C_0603]  184.25 156.33 0 bottom
C207  2200P_0402_50V7K~D  [C_0402]  95.59 81.53 0 top
C209  0.1U_0402_10V7K~D  [C_0402]  21.01 101.15 0 bottom
C210  0.1U_0402_25V6K~D  [C_0402]  16.98 28.44 0 bottom
C211  4.7U_0603_6.3V6K~D  [C_0603]  4.86 30.15 90 bottom
C212  0.1U_0402_25V6K~D  [C_0402]  5.94 30.71 90 bottom
C213  4.7U_0603_6.3V6K~D  [C_0603]  12.86 21.01 270 bottom
C214  0.1U_0402_25V6K~D  [C_0402]  9.83 22.6 180 bottom
C215  0.1U_0402_25V6K~D  [C_0402]  10.71 34.46 90 bottom
C216  0.1U_0402_25V6K~D  [C_0402]  7.83 32.95 0 bottom
C217  0.1U_0402_25V6K~D  [C_0402]  17.05 30.67 270 bottom
C218  0.1U_0402_25V6K~D  [C_0402]  8.91 23.49 0 bottom
C219  0.1U_0402_25V6K~D  [C_0402]  8.04 22.58 90 bottom
C220  4.7U_0603_6.3V6K~D  [C_0603]  7.33 34.01 0 bottom
C221  1U_0603_10V6K~D  [C_0603]  6.07 24.69 180 bottom
C223  4.7U_0603_6.3V6K~D  [C_0603]  19.47 29.96 180 bottom
C224  4.7U_0603_6.3V6K~D  [C_0603]  5.69 22.53 0 bottom
C225  4.7U_0603_6.3V6K~D  [C_0603]  4.67 25.96 0 bottom
C226  0.1U_0402_25V6K~D  [C_0402]  7.15 25.12 90 bottom
C227  1U_0402_6.3V6K~D  [C_0402]  6.01 29.85 270 bottom
C228  4.7U_0603_6.3V6K~D  [C_0603]  5.94 32.69 180 bottom
C229  0.1U_0402_25V6K~D  [C_0402]  7.73 31.68 180 bottom
C230  4.7U_0603_6.3V6K~D  [C_0603]  17.75 23.42 90 bottom
C231  0.1U_0402_25V6K~D  [C_0402]  16.67 23.66 90 bottom
C232  0.1U_0402_25V6K~D  [C_0402]  11.59 34.93 270 bottom
C233  0.1U_0402_25V6K~D  [C_0402]  12.48 34.93 270 bottom
C234  0.1U_0402_25V6K~D  [C_0402]  17.89 31.8 180 bottom
C235  0.1U_0402_10V7K~D  [C_0402]  12.74 22.58 90 bottom
C236  0.1U_0402_10V7K~D  [C_0402]  13.62 22.58 90 bottom
C237  0.1U_0402_10V7K~D  [C_0402]  11.85 22.58 90 bottom
C238  0.1U_0402_10V7K~D  [C_0402]  10.96 22.58 90 bottom
C239  0.1U_0402_25V6K~D  [C_0402]  35.03 50.49 270 bottom
C240  4.7U_0603_6.3V6K~D  [C_0603]  35.03 52.7 90 bottom
C242  0.1U_0402_10V7K~D  [C_0402]  287.74 159.31 0 bottom
C243  0.1U_0402_10V7K~D  [C_0402]  287.74 160.27 0 bottom
C246  0.1U_0402_25V6K~D  [C_0402]  18.25 66.6 0 bottom
C247  4.7U_0603_6.3V6K~D  [C_0603]  17.31 66.92 180 bottom
C248  0.047U_0402_16V4Z~D  [C_0402]  221.13 155.88 0 top
C249  0.047U_0402_16V4Z~D  [C_0402]  219.04 141.15 0 top
C250  33P_0402_50V8J~D  [C_0402]  218.99 129.65 90 top
C251  22U_0805_6.3V6M~D  [C_0805]  212.28 147.88 180 top
C252  33P_0402_50V8J~D  [C_0402]  219.94 129.65 90 top
C253  150U_D2_6.3VY_R15M~D  [C_D2]  224.91 137.43 45 bottom
C254  220U_6.3V_M  [C_MP6VLPS220MC4R2]  202.23 159.19 0 bottom
C255  5P_0402_50V8C~D  [C_0402]  18.83 27.6 90 bottom
C256  0.1U_0402_10V7K~D  [C_0402]  214.49 145.15 180 top
C257  0.1U_0402_25V6K~D  [C_0402]  293.2 156.33 0 top
C258  0.047U_0402_16V4Z~D  [C_0402]  273.23 147.44 180 bottom
C259  0.047U_0402_16V4Z~D  [C_0402]  273.23 146.55 180 bottom
C260  0.1U_0402_25V6K~D  [C_0402]  296.84 150.56 270 top
C261  0.1U_0402_25V6K~D  [C_0402]  297.79 150.56 270 top
C262  4.7U_0603_6.3V6K~D  [C_0603]  293.22 157.41 0 top
C263  1U_0402_6.3V6K~D  [C_0402]  231.24 155.91 90 top
C264  33P_0402_50V8J~D  [C_0402]  230.96 161.09 90 top
C265  33P_0402_50V8J~D  [C_0402]  235.47 161.03 90 top
C266  33P_0402_50V8J~D  [C_0402]  235.47 160.16 270 top
C267  33P_0402_50V8J~D  [C_0402]  230.96 160.23 270 top
C268  0.1U_0402_25V6K~D  [C_0402]  186.92 96.94 90 top
C269  0.1U_0402_10V7K~D  [C_0402]  21.01 95.69 0 bottom
C270  0.1U_0402_10V7K~D  [C_0402]  21 96.57 0 bottom
C271  0.1U_0402_10V7K~D  [C_0402]  20.69 93.45 0 bottom
C272  0.1U_0402_10V7K~D  [C_0402]  20.69 94.34 0 bottom
C273  0.1U_0402_25V6K~D  [C_0402]  35.03 55.16 90 bottom
C280  0.1U_0402_10V7K~D  [C_0402]  214.49 144.26 180 top
C288  10U_0805_10V6K  [C_0805]  24.39 68.63 0 top
C289  0.1U_0402_25V6K~D  [C_0402]  24.34 69.97 0 top
C290  47U_0805_6.3V6M  [C_0805]  18.64 80.29 90 top
C291  0.1U_0402_25V6K~D  [C_0402]  17.25 80.75 90 top
C292  0.1U_0402_10V7K~D  [C_0402]  23.39 75.05 0 bottom
C293  0.1U_0402_10V7K~D  [C_0402]  23.39 75.94 0 bottom
C294  0.1U_0402_10V7K~D  [C_0402]  148.82 157.65 90 top
C295  0.1U_0402_10V7K~D  [C_0402]  149.71 158.56 270 bottom
C296  0.1U_0402_10V7K~D  [C_0402]  149.71 157.65 90 top
C297  0.1U_0402_10V7K~D  [C_0402]  150.72 158.56 270 bottom
C298  0.1U_0402_10V7K~D  [C_0402]  150.72 157.65 90 top
C299  0.1U_0402_10V7K~D  [C_0402]  151.61 158.56 270 bottom
C300  0.1U_0402_10V7K~D  [C_0402]  154.53 158.56 270 bottom
C301  0.1U_0402_10V7K~D  [C_0402]  155.42 158.56 270 bottom
C302  0.1U_0402_10V7K~D  [C_0402]  148.82 158.56 270 bottom
C303  0.1U_0402_10V7K~D  [C_0402]  151.61 157.65 90 top
C304  0.1U_0402_10V7K~D  [C_0402]  152.63 158.56 270 bottom
C305  0.1U_0402_10V7K~D  [C_0402]  152.63 157.65 90 top
C306  0.1U_0402_10V7K~D  [C_0402]  153.52 158.56 270 bottom
C307  0.1U_0402_10V7K~D  [C_0402]  153.52 157.65 90 top
C308  0.1U_0402_10V7K~D  [C_0402]  154.53 157.65 90 top
C309  0.1U_0402_10V7K~D  [C_0402]  155.42 157.65 90 top
C310  0.033U_0402_16V7K~D  [C_0402]  156.33 158.55 270 bottom
C311  0.033U_0402_16V7K~D  [C_0402]  157.15 172.46 0 top
C312  0.01U_0402_16V7K~D  [C_0402]  161.71 167.49 90 top
C313  0.01U_0402_16V7K~D  [C_0402]  162.6 167.49 90 top
C314  0.01U_0402_16V7K~D  [C_0402]  162.47 164.47 270 top
C315  0.01U_0402_16V7K~D  [C_0402]  163.36 164.47 270 top
C316  1U_0402_6.3V6K~D  [C_0402]  178.36 171.57 180 top
C317  0.1U_0603_50V7K~D  [C_0603]  133.51 167.89 180 bottom
C318  0.1U_0603_50V7K~D  [C_0603]  133.51 166.62 180 bottom
C319  12P_0402_50V8J~D  [C_0402]  179.54 164.77 0 top
C328  10U_0603_6.3V6M~D  [C_0603]  160.95 86.99 180 top
C329  0.1U_0402_25V6K~D  [C_0402]  158.99 94.68 180 top
C330  0.1U_0402_25V6K~D  [C_0402]  169.07 89.42 270 top
C331  0.1U_0402_25V6K~D  [C_0402]  174.39 96.45 0 top
C332  0.1U_0402_25V6K~D  [C_0402]  158.99 102.3 180 top
C333  0.1U_0402_16V4Z~D  [C_0402]  15.52 94.16 0 top
C334  0.1U_0402_10V7K~D  [C_0402]  158.99 101.41 180 top
C336  4.7U_0603_6.3V6K~D  [C_0603]  167.99 89.4 270 top
C337  0.047U_0402_16V4Z~D  [C_0402]  177.19 93.67 0 top
C338  0.1U_0402_25V6K~D  [C_0402]  218.46 136.71 0 top
C339  33P_0402_50V8J~D  [C_0402]  158.07 95.57 0 top
C340  1U_0402_6.3V6K~D  [C_0402]  139.23 91.24 0 top
C342  1U_0402_6.3V6K~D  [C_0402]  138.98 95.63 270 top
C343  1U_0402_6.3V6K~D  [C_0402]  141.01 92.14 270 top
C344  1U_0402_6.3V6K~D  [C_0402]  138.09 95.63 270 top
C345  0.1U_0402_25V6K~D  [C_0402]  134.29 100.96 180 top
C346  0.1U_0402_25V6K~D  [C_0402]  153.58 101.59 0 top
C347  1U_0402_6.3V4Z~D  [C_0402]  136.96 102.42 180 top
C348  10U_0603_6.3V6M~D  [C_0603]  150.34 118.55 90 top
C349  0.1U_0402_25V6K~D  [C_0402]  143.36 95.32 270 top
C350  0.1U_0402_25V6K~D  [C_0402]  153.58 109.02 0 top
C351  0.1U_0402_25V6K~D  [C_0402]  149.9 111.87 90 top
C352  1U_0402_6.3V4Z~D  [C_0402]  153.58 102.48 0 top
C353  0.1U_0402_25V6K~D  [C_0402]  136.96 101.53 180 top
C354  0.1U_0402_25V6K~D  [C_0402]  136.89 107.69 180 top
C355  0.1U_0402_25V6K~D  [C_0402]  143.93 112.12 90 top
C356  0.1U_0402_25V6K~D  [C_0402]  145.95 96.32 0 top
C357  0.1U_0402_25V6K~D  [C_0402]  153.58 99.81 0 top
C358  2200P_0402_50V7K~D  [C_0402]  147.66 95.3 0 top
C359  2200P_0402_50V7K~D  [C_0402]  145.88 95.3 0 top
C360  0.1U_0402_25V6K~D  [C_0402]  136.7 110.42 180 top
C361  2200P_0402_50V7K~D  [C_0402]  148.93 96.7 0 top
C362  1U_0402_6.3V6K~D  [C_0402]  137.07 104.4 270 top
C363  4.7P_0402_50V8C~D  [C_0402]  154.49 110.8 180 top
C364  33P_0402_50V8J~D  [C_0402]  136.25 97.79 270 top
C365  33P_0402_50V8J~D  [C_0402]  136.25 94.24 270 top
C366  4.7U_0603_6.3V6K~D  [C_0603]  144.5 95.3 270 top
C367  0.1U_0402_25V6K~D  [C_0402]  153.57 98.86 0 top
C368  4700P_0402_25V7K~D  [C_0402]  144.82 88.94 90 top
C369  4700P_0402_25V7K~D  [C_0402]  144.82 92.84 270 top
C370  100P_0402_50V8J~D  [C_0402]  115.64 45.41 0 top
C371  0.1U_0402_25V6K~D  [C_0402]  153.57 112.58 0 top
C372  100P_0402_50V8J~D  [C_0402]  76.5 81.21 180 top
C373  100P_0402_50V8J~D  [C_0402]  167.33 139.32 180 top
C374  0.1U_0402_25V6K~D  [C_0402]  146.86 89.78 180 top
C375  0.1U_0402_25V6K~D  [C_0402]  179.49 108.27 270 top
C376  0.1U_0402_25V6K~D  [C_0402]  185.14 108.21 270 top
C377  10P_0402_50V8J~D  [C_0402]  182.42 99.24 180 top
C378  10P_0402_50V8J~D  [C_0402]  178.71 99.24 0 top
C379  10P_0402_50V8J~D  [C_0402]  181 104.13 0 top
C380  10P_0402_50V8J~D  [C_0402]  180.14 104.13 180 top
C382  2200P_0402_50V7K~D  [C_0402]  152.18 96.69 90 top
C383  100P_0402_50V8J~D  [C_0402]  174.55 80.29 180 bottom
C384  2200P_0402_50V7K~D  [C_0402]  159.04 108.14 270 top
C385  10U_0805_10V6K  [C_0805]  253.44 146.36 0 bottom
C386  0.1U_0402_25V6K~D  [C_0402]  140.94 117.96 90 top
C387  0.01U_0402_16V7K~D  [C_0402]  145.12 121.21 0 top
C389  1U_0603_10V6K~D  [C_0603]  91.79 74.92 180 top
C390  470P_0402_50V7K~D  [C_0402]  92.99 73.14 0 top
C391  470P_0402_50V7K~D  [C_0402]  92.99 71.94 0 top
C393  1U_0603_10V6K~D  [C_0603]  91.96 70.03 180 top
C395  47P_0402_50V8J~D  [C_0402]  136.5 113.39 90 top
C396  1U_0603_10V6K~D  [C_0603]  84.29 15.1 270 bottom
C397  470P_0402_50V7K~D  [C_0402]  85.37 15.18 270 bottom
C398  470P_0402_50V7K~D  [C_0402]  86.32 15.18 270 bottom
C399  1U_0603_10V6K~D  [C_0603]  87.46 15.17 270 bottom
C400  1U_0603_10V6K~D  [C_0603]  218.41 154.3 90 top
C401  470P_0402_50V7K~D  [C_0402]  218.91 151.06 0 top
C402  1000P_0402_50V7K~D  [C_0402]  218.91 150.17 0 top
C403  1U_0603_10V6K~D  [C_0603]  217.78 148.14 180 top
C404  0.1U_0402_25V6K~D  [C_0402]  189.84 90.53 90 top
C405  1U_0603_10V6K~D  [C_0603]  258.16 158.42 90 bottom
C406  0.1U_0402_10V7K~D  [C_0402]  171.61 146.31 270 top
C408  10U_0805_10V6K  [C_0805]  261.91 161.26 90 bottom
C409  470P_0402_50V7K~D  [C_0402]  214.15 138.48 0 top
C410  1U_0603_10V7K~D  [C_0603]  247.43 154.8 90 bottom
C412  1U_0603_10V6K~D  [C_0603]  247.69 145.98 0 bottom
C413  .47U_0402_10V6K  [C_0402]  137.3 55.32 180 top
C414  0.01U_0402_16V7K~D  [C_0402]  101.32 4 270 bottom
C422  1U_0603_10V6K~D  [C_0603]  212.51 140.64 180 top
C425  1U_0603_10V6K~D  [C_0603]  212.38 135.5 180 top
C426  1U_0603_10V6K~D  [C_0603]  199.68 170.04 0 top
C427  470P_0402_50V7K~D  [C_0402]  214.15 137.6 0 top
C430  1U_0603_10V6K~D  [C_0603]  94.46 100.83 0 top
C431  1U_0603_10V6K~D  [C_0603]  86.84 112.7 180 top
C432  1U_0603_10V6K~D  [C_0603]  190.22 26.34 180 bottom
C434  0.1U_0402_25V6K~D  [C_0402]  106.08 107.57 270 top
C435  0.1U_0402_25V6K~D  [C_0402]  96.19 108.64 180 top
C436  0.1U_0402_25V6K~D  [C_0402]  109.46 111.5 180 top
C437  22U_0603_6.3V6M~D  [C_0603]  111.16 112.45 90 top
C438  1000P_0402_50V7K~D  [C_0402]  90.59 157.01 90 bottom
C439  0.1U_0603_50V7K~D  [C_0603]  84.87 158.68 180 bottom
C440  0.1U_0402_25V6K~D  [C_0402]  97.51 143.64 270 top
C441  10U_0603_6.3V6M~D  [C_0603]  109.96 114.04 90 top
C442  0.1U_0402_25V6K~D  [C_0402]  108.88 114.28 90 top
C443  10U_0603_6.3V6M~D  [C_0603]  100.37 106.23 180 top
C444  0.1U_0402_25V6K~D  [C_0402]  100.13 107.31 180 top
C445  0.1U_0402_10V7K~D  [C_0402]  102.84 105.67 270 top
C446  0.1U_0402_10V7K~D  [C_0402]  103.73 105.67 270 top
C447  0.1U_0402_10V7K~D  [C_0402]  104.24 107.57 270 top
C448  0.1U_0402_10V7K~D  [C_0402]  105.13 107.57 270 top
C449  0.1U_0402_10V7K~D  [C_0402]  102.33 107.57 270 top
C450  0.1U_0402_10V7K~D  [C_0402]  101.44 107.57 270 top
C451  0.1U_0402_25V6K~D  [C_0402]  97.51 140.69 90 top
C452  1U_0603_10V6K~D  [C_0603]  200.95 167.5 0 top
C453  0.1U_0603_50V7K~D  [C_0603]  83.48 157.41 0 bottom
C454  0.1U_0402_25V6K~D  [C_0402]  69.95 109.33 90 top
C455  0.1U_0402_25V6K~D  [C_0402]  74.08 105.13 90 top
C456  0.1U_0402_25V6K~D  [C_0402]  73.9 100.88 270 bottom
C458  0.1U_0603_50V7K~D  [C_0603]  98.53 99.05 270 top
C459  0.1U_0603_50V7K~D  [C_0603]  99.67 95.24 90 top
C460  1U_0603_10V6K~D  [C_0603]  188.22 21.01 0 bottom
C461  1U_0603_10V6K~D  [C_0603]  95.8 98.48 270 top
C462  1U_0603_10V6K~D  [C_0603]  90.52 107.75 180 top
C482  0.1U_0402_10V7K~D  [C_0402]  306.22 166.81 0 top
C633  0.1U_0402_25V6K~D  [C_0402]  93.32 25.76 90 top
C634  0.1U_0402_25V6K~D  [C_0402]  99.34 17.45 0 top
C635  0.1U_0402_25V6K~D  [C_0402]  96.62 25.76 90 top
C636  0.1U_0402_25V6K~D  [C_0402]  97.57 25.76 90 top
C645  0.1U_0402_25V6K~D  [C_0402]  94.65 25.76 90 top
C647  0.1U_0402_10V7K~D  [C_0402]  91.73 19.5 270 bottom
C648  0.1U_0402_10V7K~D  [C_0402]  90.84 19.5 270 bottom
C809  220U_6.3V_M  [C_MP6VLPS220MC4R2]  19.91 79.94 180 bottom
C1001  0.1U_0402_25V6K~D  [C_0402]  306.22 167.69 0 top
C1185  0.1U_0402_16V4Z~D  [C_0402]  313.28 166.63 270 top
C1186  0.1U_0402_16V4Z~D  [C_0402]  92.54 86.67 0 top
C1187  0.1U_0402_16V4Z~D  [C_0402]  183.73 3.93 0 top
C1188  0.1U_0402_16V4Z~D  [C_0402]  283.44 165.42 270 bottom
C1189  0.1U_0402_16V4Z~D  [C_0402]  282.04 165.42 270 bottom
C2962  0.1U_0402_16V4Z~D  [C_0402]  296.26 165.61 270 top
C2963  0.01U_0402_16V7K~D  [C_0402]  295.31 165.61 270 top
C2964  10U_0805_10V6K  [C_0805]  294.19 165.22 180 top
C2965  0.1U_0402_16V4Z~D  [C_0402]  297.15 165.61 270 top
C2966  0.1U_0402_10V7K~D  [C_0402]  294.35 167.86 0 top
C2967  0.1U_0402_10V7K~D  [C_0402]  294.35 168.81 0 top
C2968  0.1U_0402_10V7K~D  [C_0402]  294.35 169.76 0 top
C2969  0.1U_0402_10V7K~D  [C_0402]  294.35 170.72 0 top
C2972  0.1U_0402_16V4Z~D  [C_0402]  302.6 173.84 90 top
C2980  0.1U_0603_50V7K~D  [C_0603]  313.09 153.34 90 top
C2987  0.01U_0402_16V7K~D  [C_0402]  154.48 150.87 180 top
C2988  0.01U_0402_16V7K~D  [C_0402]  159.12 156.01 180 top
C2989  0.1U_0402_25V6K~D  [C_0402]  154.48 152.9 180 top
C2990  0.1U_0402_25V6K~D  [C_0402]  158.53 149.04 270 top
C2991  0.1U_0402_25V6K~D  [C_0402]  154.48 151.88 180 top
C2992  0.1U_0402_25V6K~D  [C_0402]  162.79 155.11 90 top
C3004  1000P_0402_50V7K~D  [C_0402]  194.03 41.32 90 bottom
C3005  0.1U_0402_25V6K~D  [C_0402]  193.08 41.32 90 bottom
C3022  10U_0603_6.3V6M~D  [C_0603]  181.08 125.91 270 top
C3023  0.1U_0402_10V7K~D  [C_0402]  176.88 126.03 90 top
C3024  0.1U_0402_10V7K~D  [C_0402]  178.71 124.07 0 top
C3025  0.1U_0402_10V7K~D  [C_0402]  170.17 116.96 180 top
C3026  0.1U_0402_10V7K~D  [C_0402]  174.6 126.41 90 top
C3027  0.1U_0402_10V7K~D  [C_0402]  167.68 121.77 90 top
C3028  0.1U_0402_10V7K~D  [C_0402]  171.42 126.47 90 top
C3029  0.1U_0402_10V7K~D  [C_0402]  174.97 117.02 0 top
C3030  4.7U_0603_6.3V6K~D  [C_0603]  176.88 117.15 90 top
C3031  0.1U_0402_10V7K~D  [C_0402]  172.3 127.31 0 top
C3032  1U_0402_6.3V6K~D  [C_0402]  172.3 126.42 0 top
C3033  1U_0402_6.3V6K~D  [C_0402]  175.61 115.07 270 top
C3034  0.1U_0402_10V7K~D  [C_0402]  174.72 115.07 270 top
CC1  15P_0402_50V8J  [C_0402]  131.69 73.4 180 bottom
CC2  15P_0402_50V8J  [C_0402]  132.55 73.97 0 bottom
CC3  1U_0402_6.3V6K~D  [C_0402]  146.71 73.08 0 bottom
CC4  1U_0402_6.3V6K~D  [C_0402]  145.66 73.08 180 bottom
CC5  27P_0402_50V8J~D  [C_0402]  132.74 64.63 0 bottom
CC6  15P_0402_50V8J  [C_0402]  99.67 51.63 270 bottom
CC7  15P_0402_50V8J  [C_0402]  99.67 48.94 90 bottom
CC8  0.1U_0402_25V6K~D  [C_0402]  107.91 79.81 0 bottom
CC9  0.1U_0402_25V6K~D  [C_0402]  138.78 80.12 90 bottom
CC10  0.1U_0402_25V6K~D  [C_0402]  138.11 4.31 270 top
CC11  0.1U_0402_25V6K~D  [C_0402]  139.1 15.09 90 top
CC12  2.2U_0402_6.3V6M~D  [C_0402]  130.91 37.72 270 top
CC13  2.2U_0402_6.3V6M~D  [C_0402]  130.83 47.49 0 top
CC14  12P_0402_50V8J~D  [C_0402]  136.29 64.48 270 top
CC15  12P_0402_50V8J~D  [C_0402]  135.4 64.48 270 top
CC16  10U_0603_6.3V6M~D  [C_0603]  136.5 38.54 270 top
CC17  10U_0603_6.3V6M~D  [C_0603]  134.78 41.01 270 top
CC18  10U_0603_6.3V6M~D  [C_0603]  136.5 41.01 270 top
CC19  10U_0603_6.3V6M~D  [C_0603]  134.78 43.74 270 top
CC20  10U_0603_6.3V6M~D  [C_0603]  136.5 43.74 270 top
CC21  10U_0603_6.3V6M~D  [C_0603]  134.78 38.54 270 top
CC22  0.1U_0402_25V6K~D  [C_0402]  133.5 82.36 0 top
CC23  0.1U_0402_25V6K~D  [C_0402]  134.45 87.05 0 top
CC24  0.1U_0402_25V6K~D  [C_0402]  141.63 70.1 0 top
CC25  12P_0402_50V8J~D  [C_0402]  123.72 85.78 0 top
CC26  1U_0402_6.3V6K  [C_0402]  120.07 54.47 180 top
CC27  1U_0402_6.3V6K~D  [C_0402]  113.94 60.13 0 top
CC28  22U_0603_6.3V6M~D  [C_0603]  118.39 59.82 270 top
CC29  1U_0402_6.3V6K~D  [C_0402]  112.43 61.28 270 top
CC30  1U_0402_6.3V6K~D  [C_0402]  136.4 60.27 0 top
CC31  1U_0402_6.3V6K~D  [C_0402]  114.63 62.4 270 top
CC32  1U_0402_6.3V6K~D  [C_0402]  127.35 80.69 90 top
CC33  1U_0402_6.3V6K~D  [C_0402]  112.04 59.43 0 top
CC34  10U_0603_6.3V6M~D  [C_0603]  118.53 57.33 180 top
CC35  1U_0402_6.3V6K~D  [C_0402]  132.74 69.16 0 bottom
CC36  0.1U_0402_10V7K~D  [C_0402]  120.91 62.17 270 top
CC37  1U_0402_6.3V6K~D  [C_0402]  119.58 62.17 270 top
CC38  0.1U_0402_10V7K~D  [C_0402]  132.74 68.27 0 bottom
CC39  0.1U_0402_10V7K~D  [C_0402]  132.57 65.46 180 top
CC40  0.1U_0402_10V7K~D  [C_0402]  117.5 61.67 270 top
CC41  0.1U_0402_25V6K~D  [C_0402]  108.99 13.01 0 bottom
CC42  22U_0603_6.3V6M~D  [C_0603]  98.78 57.81 90 bottom
CC43  22U_0603_6.3V6M~D  [C_0603]  117.18 59.82 270 top
CC44  0.1U_0402_10V7K~D  [C_0402]  120.19 55.81 180 top
CC45  1U_0402_6.3V6K~D  [C_0402]  115.86 59.12 270 top
CC46  1U_0402_6.3V6K~D  [C_0402]  119.85 60.38 0 top
CC47  22U_0805_6.3V6M~D  [C_0805]  131.36 58.88 270 top
CC48  0.1U_0402_25V6K~D  [C_0402]  137.05 15.09 90 top
CC49  22U_0603_6.3V6M~D  [C_0603]  98.97 62.41 90 bottom
CC50  22U_0603_6.3V6M~D  [C_0603]  119.93 53.01 270 top
CC51  1U_0402_6.3V6K~D  [C_0402]  112.09 56.52 270 top
CC52  2.2U_0402_6.3V6M~D  [C_0402]  131.75 44.31 180 top
CC53  1U_0402_6.3V6K~D  [C_0402]  118.39 61.67 270 top
CC54  1U_0402_6.3V6K~D  [C_0402]  119.72 65.65 0 top
CC55  100U_1206_6.3V6M  [C_1206]  92.87 52.12 270 top
CC56  1U_0402_6.3V6K~D  [C_0402]  117.49 55.79 0 top
CC57  12P_0402_50V8J~D  [C_0402]  123.72 84.83 0 top
CC58  1U_0402_6.3V6K~D  [C_0402]  100.43 55.67 90 top
CC59  0.1U_0402_10V7K~D  [C_0402]  114.85 59.12 270 top
CC60  1U_0402_6.3V6K~D  [C_0402]  119.48 57.26 90 top
CC61  1U_0402_6.3V6K~D  [C_0402]  100.11 62.11 270 top
CC62  10U_0603_6.3V6M~D  [C_0603]  100.11 63.05 90 top
CC63  1U_0402_6.3V6K~D  [C_0402]  113.73 57.57 90 top
CC64  1U_0402_6.3V6K~D  [C_0402]  114.75 54.43 0 top
CC65  1U_0402_6.3V6K~D  [C_0402]  137.31 57.57 180 top
CC66  1U_0402_6.3V6K~D  [C_0402]  120.56 59.5 270 top
CC67  0.022U_0402_16V7K~D  [C_0402]  159.49 24.49 90 top
CC68  0.01U_0402_16V7K~D  [C_0402]  136.33 4.33 270 top
CC69  0.022U_0402_16V7K~D  [C_0402]  155.17 9.5 90 top
CC70  0.022U_0402_16V7K~D  [C_0402]  159.93 12.2 270 top
CC71  330U_D3_2.5VY_R6M  [C_D2]  88.72 65.76 135 top
CC73  330U_D3_2.5VY_R6M  [C_D2]  132.08 90.54 180 top
CC74  1U_0402_6.3V6K~D  [C_0402]  111.82 64.79 90 top
CC75  100U_1206_6.3V6M  [C_1206]  94.08 66.03 270 top
CC76  22U_0603_6.3V6M~D  [C_0603]  97.51 57.81 90 bottom
CC77  22U_0603_6.3V6M~D  [C_0603]  97.76 62.41 90 bottom
CC78  100U_1206_6.3V6M  [C_1206]  98.08 56.38 270 top
CC79  100U_1206_6.3V6M  [C_1206]  98.59 57.78 90 top
CC80  12P_0402_50V8J~D  [C_0402]  135.37 86.16 180 top
CC81  2.2U_0402_6.3V6M~D  [C_0402]  130.83 40.57 0 top
CC82  0.1U_0402_25V6K~D  [C_0402]  135.29 75.16 90 bottom
CC84  27P_0402_50V8J~D  [C_0402]  160.5 106.37 270 top
CC85  18P_0402_50V8J~D  [C_0402]  173.84 114.62 270 top
CC86  18P_0402_50V8J~D  [C_0402]  171.44 115.5 180 top
CD1  2.2U_0402_6.3V6M~D  [C_0402]  172.32 8.83 90 top
CD2  0.1U_0402_25V6K~D  [C_0402]  173.21 8.83 90 top
CD3  0.1U_0402_25V6K~D  [C_0402]  185.86 17.42 270 top
CD4  1U_0402_6.3V6K~D  [C_0402]  176.26 41.46 180 top
CD5  1U_0402_6.3V6K~D  [C_0402]  176.07 37.39 180 top
CD6  1U_0402_6.3V6K~D  [C_0402]  184.05 34.09 0 top
CD7  1U_0402_6.3V6K~D  [C_0402]  183.86 41.52 0 top
CD8  1U_0402_6.3V6K~D  [C_0402]  183.73 37.52 0 top
CD9  1U_0402_6.3V6K~D  [C_0402]  175.22 33.77 0 top
CD10  1U_0402_6.3V6K~D  [C_0402]  183.92 44.5 0 top
CD11  1U_0402_6.3V6K~D  [C_0402]  175.6 45.9 0 top
CD12  2.2U_0402_6.3V6M~D  [C_0402]  183.68 49 90 top
CD13  0.1U_0402_25V6K~D  [C_0402]  184.57 49 90 top
CD14  10U_0603_6.3V6M~D  [C_0603]  183.55 35.17 0 top
CD15  10U_0603_6.3V6M~D  [C_0603]  183.42 38.66 0 top
CD16  10U_0603_6.3V6M~D  [C_0603]  176.63 38.54 180 top
CD17  10U_0603_6.3V6M~D  [C_0603]  175.23 32.69 0 top
CD18  10U_0603_6.3V6M~D  [C_0603]  176.76 42.66 180 top
CD19  10U_0603_6.3V6M~D  [C_0603]  183.61 42.6 0 top
CD20  10U_0603_6.3V6M~D  [C_0603]  183.36 45.58 0 top
CD21  10U_0603_6.3V6M~D  [C_0603]  175.04 44.82 0 top
CD22  330U_D3_2.5VY_R6M  [C_D3]  162.05 52.06 180 top
CD23  0.1U_0402_25V6K~D  [C_0402]  189.07 37.6 270 top
CD24  0.1U_0402_25V6K~D  [C_0402]  173.31 73.14 0 top
CD25  2.2U_0402_6.3V6M~D  [C_0402]  173.31 72.25 0 top
CD26  0.1U_0402_25V6K~D  [C_0402]  184.33 72.33 90 top
CD27  0.1U_0402_25V6K~D  [C_0402]  183.44 72.33 90 top
CD28  0.1U_0402_25V6K~D  [C_0402]  176.06 73.09 270 top
CD29  0.1U_0402_25V6K~D  [C_0402]  175.1 73.09 270 top
CD30  10U_0603_6.3V6M~D  [C_0603]  177.14 73.59 270 top
CD31  10U_0603_6.3V6M~D  [C_0603]  182.34 72.38 90 top
CD32  2.2U_0402_6.3V6M~D  [C_0402]  163.48 8.74 90 top
CD33  0.1U_0402_25V6K~D  [C_0402]  162.6 8.74 90 top
CD34  0.1U_0402_25V6K~D  [C_0402]  172.83 17.07 180 top
CD35  1U_0402_6.3V6K~D  [C_0402]  162.86 45.52 180 top
CD36  1U_0402_6.3V6K~D  [C_0402]  163.12 38.28 180 top
CD37  1U_0402_6.3V6K~D  [C_0402]  161.95 34.34 0 top
CD38  1U_0402_6.3V6K~D  [C_0402]  162.67 42.85 180 top
CD39  1U_0402_6.3V6K~D  [C_0402]  167.62 44.12 180 top
CD40  1U_0402_6.3V6K~D  [C_0402]  170.33 33.39 0 top
CD41  1U_0402_6.3V6K~D  [C_0402]  170.2 37.52 0 top
CD42  1U_0402_6.3V6K~D  [C_0402]  170.39 41.52 0 top
CD43  2.2U_0402_6.3V6M~D  [C_0402]  175.04 51.67 90 top
CD44  0.1U_0402_25V6K~D  [C_0402]  175.93 51.67 90 top
CD45  10U_0603_6.3V6M~D  [C_0603]  167.87 46.85 180 top
CD46  10U_0603_6.3V6M~D  [C_0603]  169.96 42.66 0 top
CD47  10U_0603_6.3V6M~D  [C_0603]  169.64 38.73 0 top
CD48  10U_0603_6.3V6M~D  [C_0603]  169.83 34.53 0 top
CD49  10U_0603_6.3V6M~D  [C_0603]  163.1 46.66 180 top
CD50  10U_0603_6.3V6M~D  [C_0603]  163.17 43.93 180 top
CD51  10U_0603_6.3V6M~D  [C_0603]  163.29 39.42 180 top
CD52  10U_0603_6.3V6M~D  [C_0603]  161.71 35.55 0 top
CD54  0.1U_0402_25V6K~D  [C_0402]  168.57 71.57 270 top
CD55  0.1U_0402_25V6K~D  [C_0402]  167.42 71.57 270 top
CD56  0.1U_0402_25V6K~D  [C_0402]  166.28 71.57 270 top
CD57  0.1U_0402_25V6K~D  [C_0402]  163.42 72.88 90 top
CD58  10U_0603_6.3V6M~D  [C_0603]  162.34 72.64 90 top
CD59  10U_0603_6.3V6M~D  [C_0603]  170.47 71.62 270 top
CD60  0.1U_0402_25V6K~D  [C_0402]  161.21 72.64 180 top
CD61  2.2U_0402_6.3V6M~D  [C_0402]  161.21 71.68 180 top
CD62  330U_D3_2.5VY_R6M  [C_D3]  189.66 35.46 270 bottom
CE7  4.7U_0805_25V6K~D  [C_0805]  133.67 165.09 180 bottom
CE8  4.7P_0402_50V8C~D  [C_0402]  169.35 164.46 270 top
CE9  4.7P_0402_50V8C~D  [C_0402]  166.53 163.62 90 top
CE10  100P_0402_50V8J~D  [C_0402]  104.05 135.96 270 top
CE11  100P_0402_50V8J~D  [C_0402]  102.58 139.75 0 top
CE14  0.1U_0402_25V6K~D  [C_0402]  88.17 25.76 90 top
CE20  0.1U_0402_25V6K~D  [C_0402]  89.13 25.76 90 top
CE22  0.1U_0402_25V6K~D  [C_0402]  91.99 25.76 90 top
CMOS1  SHORT PADS~D  [SHORTPADS]  144.94 71.94 180 bottom
CS1  0.01U_0402_16V7K~D  [C_0402]  193.38 26.66 0 bottom
CS2  0.01U_0402_16V7K~D  [C_0402]  193.38 27.61 0 bottom
CS3  0.01U_0402_16V7K~D  [C_0402]  193.64 30.41 0 bottom
CS4  0.01U_0402_16V7K~D  [C_0402]  193.64 31.3 0 bottom
